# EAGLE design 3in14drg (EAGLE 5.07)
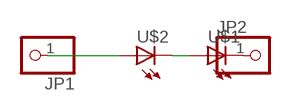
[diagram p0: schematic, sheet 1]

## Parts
JP1  PINHD-1X11X0.4  [1X01]
JP2  PINHD-1X11X0.4  [1X01]
U$1  LEDSMT1206  [1206]
U$2  LEDSMT1206  [1206]

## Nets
N$1: JP1.1 U$2.A
N$3: U$1.A U$2.C
N$4: JP2.1 U$1.C

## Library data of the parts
JP1 JP2 = pinhead:PINHD-1X1: PIN HEADER
U$1 U$2 = led(2):LED: LED

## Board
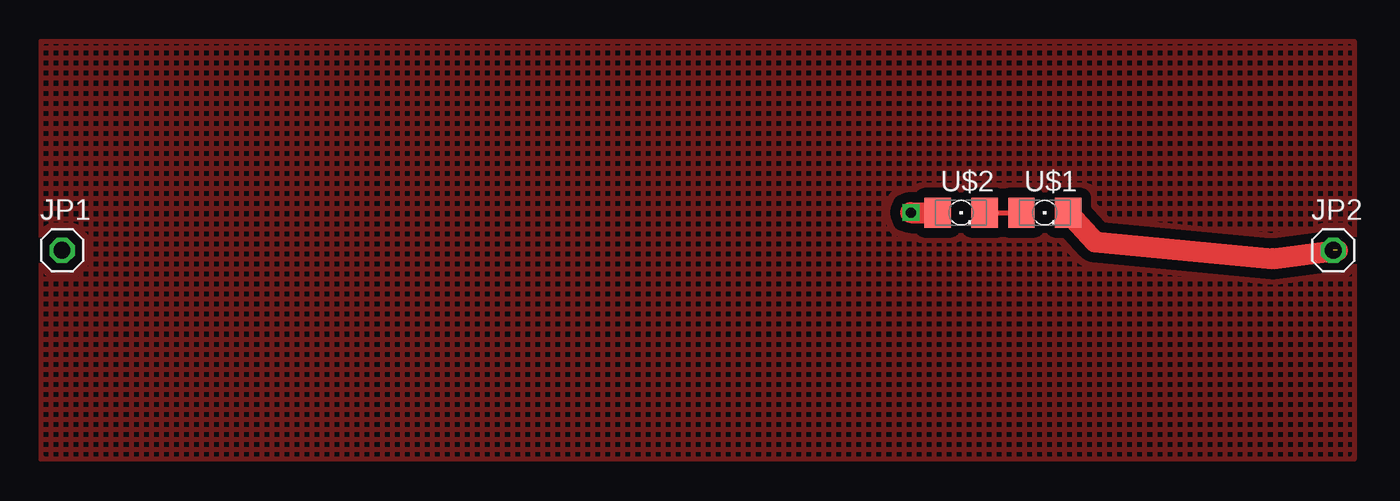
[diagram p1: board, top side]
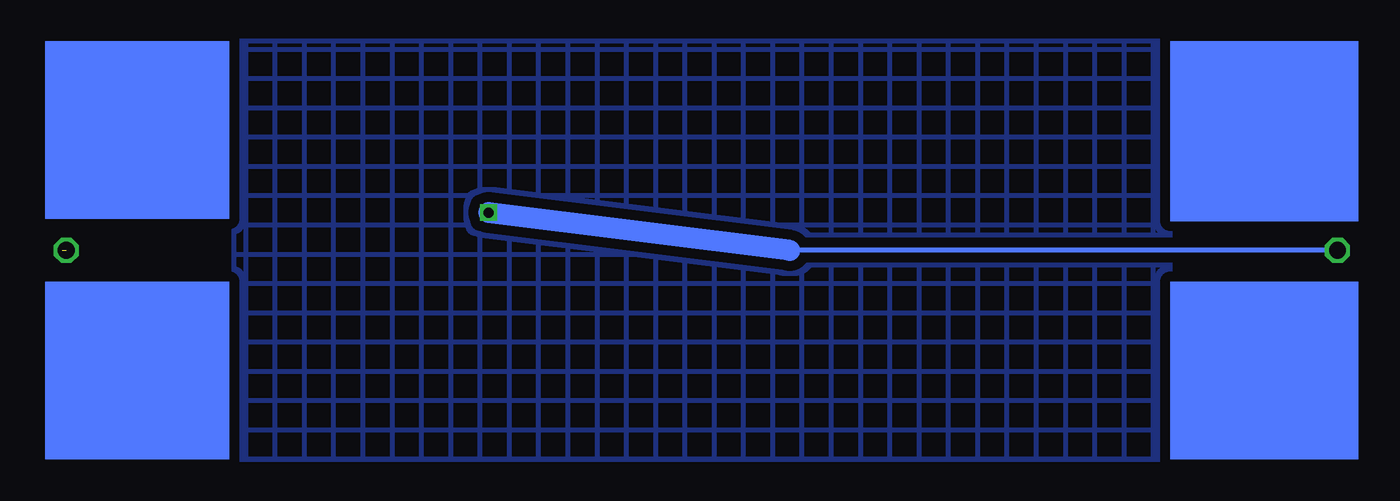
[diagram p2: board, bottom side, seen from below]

No outline drawn. Coordinates in mm, seen from the top.
Copper layers (1*16): Top 0.035mm / dielectric 1.5mm / Bottom 0.035mm
Design rules "default": minimum track width 10mil, minimum drill 24mil, track to track 8mil, track to pad 8mil, pad to pad 8mil, via to via 8mil, smd to smd 8mil, copper to edge 40mil, drill to drill 8mil, minimum pad ring 10mil, minimum via ring 8mil, stop-mask expansion 4mil, vias tented up to drill 0mil, thermal gap 10mil

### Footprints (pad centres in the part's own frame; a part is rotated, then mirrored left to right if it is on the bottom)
1X01 = drill 1.016 octagon: 1 0,0
1206 = smd 1.6 x 1.803: A -1.422,0; C 1.422,0

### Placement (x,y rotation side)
JP1  1.27,12.7 0 top
JP2  78.49,12.7 0 top
U$1  60.96,14.99 0 top
U$2  55.88,14.99 0 top

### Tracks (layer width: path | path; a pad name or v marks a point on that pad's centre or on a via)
N$1  (via drill 0.6)
  Top 1.27: v52.83,14.99 U$2.A
  Bottom 0.305: JP1.1 34.54,12.7
  Bottom 1.27: 34.54,12.7 v52.83,14.99
N$2
  pour Top (isolate 0.61, hatched): 0,25.4 79.76,25.4 79.76,0 0,0
  pour Bottom (isolate 0.61, hatched): 11.43,25.4 68.33,25.4 68.33,0 11.43,0
N$3
  Top 0.305: U$2.C U$1.A
N$4  (1 unrouted)
  Top 1.27: U$1.C 64.01,13.21 74.8,12.19 78.74,12.7
(copper drawn outside any net)
  shapes: Bottom area x4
